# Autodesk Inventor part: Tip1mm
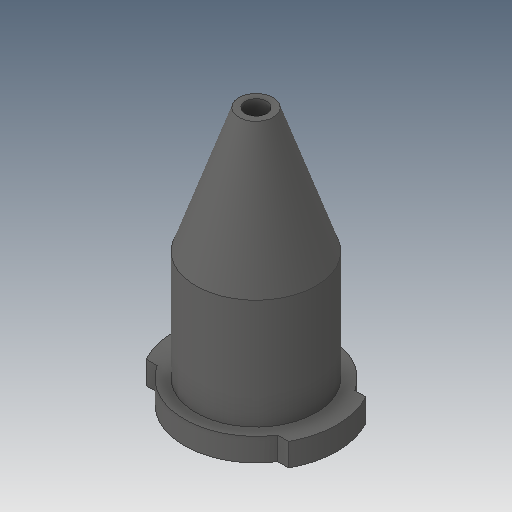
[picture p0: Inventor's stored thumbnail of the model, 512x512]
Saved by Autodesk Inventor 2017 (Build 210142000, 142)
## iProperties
Created: 2018-10
Part Number: Tip1mm
Material: Polystyrene, Expanded
Document SubType Name: Modeling
Designer: JK
Density: 0.05 g/cm^3
Appearance: Gray
Author: JK
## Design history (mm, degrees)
sketch "Sketch1"
  geometry: C1 r 2.8 at (0, 0); 1 further point
  constraints: 1 centre point
  dimensions: "d1" = 5.6 diameter of C1
extrude "Extrusion1" new body sketch "Sketch1" distance "d2" = 12; taper "d3" = 0 deg
sketch "Sketch2"
  geometry: C1 r 2.135 at (0, 0); 1 further point
  constraints: 1 centre point, 1 coincident
  dimensions: "d4" = 4.27 diameter of C1
extrude "Extrusion2" cut sketch "Sketch2" distance "d5" = 3.5; taper "d6" = 0 deg
sketch "Sketch3"
  geometry: C1 r 2.135 at (0, 0); 1 further point
  constraints: 1 centre point, 1 coincident
extrude "Extrusion3" cut sketch "Sketch3" distance "d7" = 5; taper "d8" = -5 deg
sketch "Sketch5"
  geometry: L1 (3.78, -1.8)-(-3.78, 1.8); L2 (-3.78, -1.8)-(3.78, 1.8); L3 (-3.78, 1.8)-(-2.808, 1.8); L4 (2.808, 1.8)-(3.324, 1.8); L5 (3.324, -1.8)-(2.808, -1.8); L6 (-2.808, -1.8)-(-3.324, -1.8); C1 r 2.8 at (0, 0) reference; A1 r 3.78 centre (0, 0) between (3.324, -1.8) and (3.324, 1.8); A2 r 3.78 centre (0, 0) between (-3.324, 1.8) and (-3.324, -1.8); A3 r 3.335 centre (0, 0) between (-2.808, -1.8) and (2.808, -1.8); A4 r 3.335 centre (0, 0) between (2.808, 1.8) and (-2.808, 1.8)
  constraints: 12 end point, 8 point on circle, 4 centre point, 4 parallel, 2 horizontal, 2 midpoint, 1 coincident, 1 point on line
  dimensions: "d30" = 7.56 distance of L1.end L2.end; "d31" = 3.6 distance of L2.start L1.end
extrude "Extrusion6" join sketch "Sketch5" distance "d32" = 1.07; taper "d33" = 0 deg
sketch "Sketch6"
  geometry: C1 r 0.5 at (0, 0); 1 further point
  constraints: 1 centre point, 1 coincident
  dimensions: "d34" = 1 diameter of C1
extrude "Extrusion7" cut sketch "Sketch6" stored distance "d35" = 7.18; taper "d36" = 19 deg
chamfer "Chamfer4" distance "d37" = 2; stored, may be unused: second distance "d38" = 2, angle "d39" = 71 deg
body "Solid1"
other parameters: "d28" = 6.67, "d29" = 7.56
